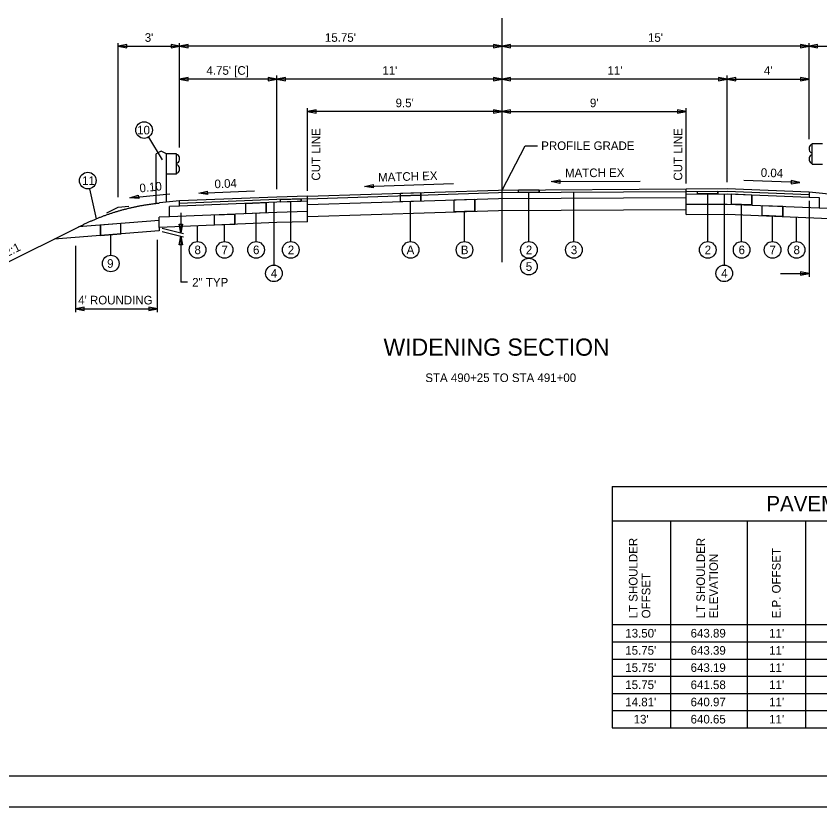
# Model space of a CAD drawing. Extents: x 0 to 102, y 0 to 66.
# Drawn here: x 34 to 73.27, y 0 to 38.63 of the extents above; entities that cross this region are included whole.
import ezdxf

# ---------------------------------------------------------------- set-up
doc = ezdxf.new("R2010")
doc.units = 0
for name, color, linetype in [('SH_Border', 7, 'Continuous'), ('SH_Cut_Line', 7, 'Continuous'), ('SH_Data', 7, 'Continuous'), ('SH_Text', 7, 'Continuous'), ('TX_P_1', 7, 'Continuous'), ('TX_X_1', 7, 'Continuous'), ('XS_P_Finished_Grade', 7, 'Continuous'), ('XS_P_Pavt_Surface', 7, 'Continuous'), ('XS_X_Pavt', 7, 'Continuous')]:
    doc.layers.add(name, color=color, linetype=linetype)

msp = doc.modelspace()

# ---------------------------------------------------------------- linework, layer by layer
at = {"layer": 'SH_Border'}
msp.add_lwpolyline([(4.5, 64.5), (100.5, 64.5), (100.5, 1.5), (4.5, 1.5)], close=True, dxfattribs=at)
at = {"layer": 'SH_Cut_Line'}
msp.add_lwpolyline([(0, 0), (102, 0), (102, 66), (0, 66)], close=True, dxfattribs=at)
at = {"layer": 'TX_P_1'}
for p, q in [((38.992, 29.793), (38.992, 37.304)), ((38.992, 37.166), (41.992, 37.166)), ((39.412, 37.082), (39.412, 37.25)), ((41.572, 37.25), (41.572, 37.082)), ((41.572, 37.25), (41.572, 37.082)), ((41.992, 32.207), (41.992, 37.304)), ((57.742, 37.166), (41.992, 37.166)), ((42.412, 37.082), (42.412, 37.25)), ((57.322, 37.25), (57.322, 37.082)), ((72.742, 37.166), (57.742, 37.166)), ((58.162, 37.082), (58.162, 37.25)), ((72.322, 37.25), (72.322, 37.082)), ((72.742, 32.62), (72.742, 37.304)), ((72.742, 37.166), (75.742, 37.166)), ((73.162, 37.082), (73.162, 37.25)), ((46.742, 35.557), (41.992, 35.557)), ((42.412, 35.473), (42.412, 35.641)), ((46.322, 35.641), (46.322, 35.473)), ((46.742, 30.182), (46.742, 35.728)), ((57.742, 35.557), (46.742, 35.557)), ((47.162, 35.473), (47.162, 35.641)), ((57.322, 35.641), (57.322, 35.473)), ((68.742, 35.557), (57.742, 35.557)), ((58.162, 35.473), (58.162, 35.641)), ((68.322, 35.641), (68.322, 35.473)), ((68.742, 30.527), (68.742, 35.728)), ((68.742, 35.557), (72.742, 35.557)), ((69.162, 35.473), (69.162, 35.641)), ((72.322, 35.641), (72.322, 35.473)), ((48.242, 30.101), (48.242, 34.133)), ((57.742, 33.972), (48.242, 33.972)), ((48.662, 33.888), (48.662, 34.056)), ((57.322, 34.056), (57.322, 33.888)), ((57.742, 33.972), (66.742, 33.972)), ((58.162, 33.888), (58.162, 34.056)), ((66.322, 34.056), (66.322, 33.888)), ((66.742, 30.461), (66.742, 34.133)), ((57.742, 30.137), (58.87, 32.301)), ((58.87, 32.301), (59.476, 32.301)), ((51.023, 30.312), (55.366, 30.45)), ((51.44, 30.409), (51.446, 30.241)), ((60.144, 30.545), (64.489, 30.571)), ((60.564, 30.631), (60.565, 30.463)), ((72.288, 30.499), (69.56, 30.608)), ((71.872, 30.6), (71.865, 30.432)), ((39.564, 29.757), (41.517, 29.952)), ((39.973, 29.882), (39.99, 29.715)), ((42.927, 29.98), (45.655, 30.089)), ((43.343, 30.081), (43.35, 29.913)), ((52.777, 29.567), (52.777, 29.984)), ((53.777, 29.599), (53.777, 30.015)), ((58.553, 30.017), (58.553, 30.142)), ((59.553, 30.023), (59.553, 30.148)), ((55.409, 29.067), (55.409, 29.651)), ((56.409, 29.099), (56.409, 29.682)), ((72.742, 29.608), (72.742, 25.893)), ((42.053, 29.022), (42.053, 28.049)), ((40.992, 28.647), (37.051, 28.331)), ((40.992, 28.312), (40.992, 28.145)), ((41.132, 28.277), (42.172, 28.019)), ((41.969, 28.469), (42.137, 28.469)), ((40.992, 28.145), (35.857, 27.734)), ((41.132, 28.11), (42.178, 27.851)), ((40.914, 24.172), (40.914, 27.706)), ((42.053, 27.882), (42.053, 25.63)), ((36.914, 24.172), (36.914, 27.403)), ((42.137, 27.462), (41.969, 27.462)), ((71.35, 26.062), (72.742, 26.062)), ((72.322, 26.146), (72.322, 25.978)), ((42.373, 25.63), (42.053, 25.63)), ((37.334, 24.254), (37.334, 24.422)), ((40.494, 24.422), (40.494, 24.254)), ((36.914, 24.338), (40.914, 24.338)), ((63.115, 15.657), (63.115, 3.866)), ((63.115, 15.657), (93.265, 15.657)), ((63.115, 13.977), (93.265, 13.977)), ((65.965, 13.977), (65.965, 3.866)), ((69.715, 13.977), (69.715, 3.866)), ((72.565, 13.977), (72.565, 3.866)), ((63.115, 8.906), (93.265, 8.906)), ((63.115, 8.066), (93.265, 8.066)), ((63.115, 7.226), (93.265, 7.226)), ((63.115, 6.386), (93.265, 6.386)), ((63.115, 5.546), (93.265, 5.546)), ((63.115, 4.706), (93.265, 4.706)), ((63.115, 3.866), (93.265, 3.866))]:
    msp.add_line(p, q, dxfattribs=at)
for points in [[(39.412, 37.25), (38.992, 37.166), (39.412, 37.082)], [(41.572, 37.082), (41.992, 37.166), (41.572, 37.25)], [(41.572, 37.082), (41.992, 37.166), (41.572, 37.25)], [(42.412, 37.25), (41.992, 37.166), (42.412, 37.082)], [(57.322, 37.082), (57.742, 37.166), (57.322, 37.25)], [(58.162, 37.25), (57.742, 37.166), (58.162, 37.082)], [(72.322, 37.082), (72.742, 37.166), (72.322, 37.25)], [(73.162, 37.25), (72.742, 37.166), (73.162, 37.082)], [(42.412, 35.641), (41.992, 35.557), (42.412, 35.473)], [(46.322, 35.473), (46.742, 35.557), (46.322, 35.641)], [(47.162, 35.641), (46.742, 35.557), (47.162, 35.473)], [(57.322, 35.473), (57.742, 35.557), (57.322, 35.641)], [(58.162, 35.641), (57.742, 35.557), (58.162, 35.473)], [(68.322, 35.473), (68.742, 35.557), (68.322, 35.641)], [(69.162, 35.641), (68.742, 35.557), (69.162, 35.473)], [(72.322, 35.473), (72.742, 35.557), (72.322, 35.641)], [(48.662, 34.056), (48.242, 33.972), (48.662, 33.888)], [(57.322, 33.888), (57.742, 33.972), (57.322, 34.056)], [(58.162, 34.056), (57.742, 33.972), (58.162, 33.888)], [(66.322, 33.888), (66.742, 33.972), (66.322, 34.056)], [(51.446, 30.241), (51.023, 30.312), (51.44, 30.409)], [(60.565, 30.463), (60.144, 30.545), (60.564, 30.631)], [(71.865, 30.432), (72.288, 30.499), (71.872, 30.6)], [(39.99, 29.715), (39.564, 29.757), (39.973, 29.882)], [(43.35, 29.913), (42.927, 29.98), (43.343, 30.081)], [(38.428, 29.02), (38.992, 29.302), (39.51, 29.354)], [(42.137, 28.469), (42.053, 28.049), (41.969, 28.469)], [(41.969, 27.462), (42.053, 27.882), (42.137, 27.462)], [(72.322, 25.978), (72.742, 26.062), (72.322, 26.146)], [(37.334, 24.422), (36.914, 24.338), (37.334, 24.254)], [(40.494, 24.254), (40.914, 24.338), (40.494, 24.422)]]:
    msp.add_lwpolyline(points, dxfattribs=at)
for points in [[(52.777, 29.984), (53.777, 30.015), (53.777, 29.89), (52.777, 29.859)], [(53.777, 29.599), (52.777, 29.567), (52.777, 29.859), (53.777, 29.89)], [(59.553, 30.023), (58.553, 30.017), (58.553, 30.142), (59.553, 30.148)], [(56.409, 29.682), (56.409, 29.099), (55.409, 29.067), (55.409, 29.651)]]:
    msp.add_lwpolyline(points, close=True, dxfattribs=at)
for centre in [(40.253, 33.064), (37.504, 30.597), (42.867, 27.212), (44.188, 27.212), (45.726, 27.212), (47.422, 27.212), (53.277, 27.212), (55.909, 27.212), (59.053, 27.212), (61.252, 27.212), (67.791, 27.212), (69.449, 27.212), (70.959, 27.212), (72.135, 27.212), (38.623, 26.547), (59.053, 26.399), (46.596, 26.066), (68.598, 26.066)]:
    msp.add_circle(centre, 0.406, dxfattribs=at)
at = {"layer": 'TX_X_1'}
for p, q in [((57.742, 26.608), (57.742, 38.528)), ((40.465, 32.717), (41.143, 31.614)), ((37.593, 30.2), (37.921, 28.733)), ((59.053, 27.618), (59.053, 30.02)), ((61.252, 27.618), (61.252, 30.033)), ((67.291, 29.945), (67.291, 30.07)), ((67.791, 27.618), (67.791, 29.948)), ((68.291, 29.951), (68.291, 30.076)), ((68.598, 29.953), (68.598, 26.472)), ((68.949, 29.445), (68.949, 29.945)), ((69.949, 29.405), (69.949, 29.905)), ((45.226, 28.981), (45.226, 29.481)), ((46.226, 29.021), (46.226, 29.521)), ((46.596, 29.536), (46.596, 26.472)), ((46.922, 29.548), (46.922, 29.673)), ((47.422, 27.618), (47.422, 29.563)), ((47.922, 29.579), (47.922, 29.704)), ((53.277, 27.618), (53.277, 29.583)), ((55.909, 27.618), (55.909, 29.083)), ((69.449, 27.618), (69.449, 29.425)), ((70.459, 28.885), (70.459, 29.385)), ((71.459, 28.845), (71.459, 29.345)), ((43.688, 28.42), (43.688, 28.92)), ((44.688, 28.46), (44.688, 28.96)), ((45.726, 27.618), (45.726, 29.001)), ((70.959, 27.618), (70.959, 28.865)), ((72.135, 27.618), (72.135, 28.818)), ((38.123, 27.916), (38.123, 28.417)), ((39.123, 27.996), (39.123, 28.497)), ((42.867, 27.618), (42.867, 28.387)), ((44.188, 27.618), (44.188, 28.44)), ((38.623, 26.953), (38.623, 27.956))]:
    msp.add_line(p, q, dxfattribs=at)
for points in [[(48.242, 29.839), (57.57, 30.136), (66.742, 30.192)], [(48.242, 29.423), (57.57, 29.719), (66.742, 29.775)], [(48.242, 28.839), (57.57, 29.136), (66.742, 29.192)]]:
    msp.add_lwpolyline(points, dxfattribs=at)
for points in [[(68.291, 29.951), (67.291, 29.945), (67.291, 30.07), (68.291, 30.076)], [(69.949, 29.405), (68.949, 29.445), (68.949, 29.945), (69.949, 29.905)], [(45.226, 28.981), (45.226, 29.481), (46.226, 29.521), (46.226, 29.021)], [(46.922, 29.548), (46.922, 29.673), (47.922, 29.704), (47.922, 29.579)], [(71.459, 29.345), (71.459, 28.845), (70.459, 28.885), (70.459, 29.385)], [(44.688, 28.96), (44.688, 28.46), (43.688, 28.42), (43.688, 28.92)], [(38.123, 28.417), (38.123, 27.916), (39.123, 27.996), (39.123, 28.497)]]:
    msp.add_lwpolyline(points, close=True, dxfattribs=at)
at = {"layer": 'XS_P_Finished_Grade'}
for p, q in [((72.742, 30.043), (75.742, 29.743)), ((41.992, 29.602), (41.015, 29.504)), ((37.173, 28.392), (30.605, 25.108))]:
    msp.add_line(p, q, dxfattribs=at)
msp.add_spline([(37.173, 28.392), (37.243, 28.427), (37.313, 28.461), (37.383, 28.495), (37.454, 28.528), (37.524, 28.561), (37.595, 28.593), (37.666, 28.624), (37.737, 28.655), (37.808, 28.686), (37.88, 28.716), (37.951, 28.745), (38.023, 28.774), (38.095, 28.803), (38.167, 28.831), (38.239, 28.858), (38.311, 28.885), (38.384, 28.911), (38.456, 28.937), (38.529, 28.963), (38.602, 28.987), (38.675, 29.012), (38.748, 29.035), (38.822, 29.059), (38.895, 29.081), (38.969, 29.103), (39.043, 29.125), (39.117, 29.146), (39.191, 29.167), (39.265, 29.187), (39.339, 29.206), (39.414, 29.225), (39.489, 29.244), (39.564, 29.262), (39.639, 29.279), (39.714, 29.296), (39.789, 29.313), (39.865, 29.329), (39.94, 29.344), (40.016, 29.359), (40.092, 29.373), (40.168, 29.387), (40.244, 29.4), (40.321, 29.413), (40.397, 29.425), (40.474, 29.437), (40.551, 29.448), (40.628, 29.459), (40.705, 29.469), (40.782, 29.478), (40.86, 29.488), (40.937, 29.496), (41.015, 29.504)], degree=3, dxfattribs=at)
at = {"layer": 'XS_P_Pavt_Surface'}
for p, q in [((66.742, 30.192), (68.742, 30.203)), ((66.742, 28.942), (66.742, 30.192)), ((66.742, 30.067), (68.742, 30.078)), ((66.742, 30.067), (68.742, 30.078)), ((66.742, 29.942), (68.742, 29.953)), ((68.742, 30.203), (72.742, 30.043)), ((68.742, 30.078), (72.742, 29.918)), ((68.742, 30.078), (72.742, 29.918)), ((68.742, 29.953), (72.742, 29.793)), ((72.742, 30.043), (72.742, 29.793)), ((46.742, 29.792), (41.992, 29.602)), ((46.742, 29.667), (41.992, 29.477)), ((46.742, 29.667), (41.992, 29.477)), ((41.992, 29.352), (41.992, 29.602)), ((46.742, 29.542), (41.992, 29.352)), ((48.242, 29.839), (46.742, 29.792)), ((48.242, 29.714), (46.742, 29.667)), ((48.242, 29.714), (46.742, 29.667)), ((48.242, 29.589), (46.742, 29.542)), ((48.242, 28.589), (48.242, 29.839)), ((72.742, 29.793), (73.242, 29.773)), ((73.242, 29.773), (73.242, 29.273)), ((41.992, 29.352), (41.492, 29.332)), ((41.492, 28.832), (41.492, 29.332)), ((48.242, 29.089), (46.742, 29.042)), ((66.742, 29.442), (68.742, 29.453)), ((68.742, 29.453), (73.242, 29.273)), ((73.242, 29.273), (73.742, 29.253)), ((41.492, 28.832), (40.992, 28.812)), ((40.992, 28.312), (40.992, 28.812)), ((46.742, 29.042), (41.492, 28.832)), ((66.742, 28.942), (68.742, 28.953)), ((68.742, 28.953), (73.742, 28.753)), ((46.742, 28.542), (40.992, 28.312)), ((48.242, 28.589), (46.742, 28.542))]:
    msp.add_line(p, q, dxfattribs=at)
for points in [[(48.242, 29.839), (57.57, 30.136), (66.742, 30.192)], [(48.242, 29.714), (57.57, 30.011), (66.742, 30.067)]]:
    msp.add_lwpolyline(points, dxfattribs=at)
at = {"layer": 'XS_X_Pavt'}
for p, q in [((72.842, 32.354), (72.892, 32.354)), ((72.892, 31.404), (72.892, 32.404)), ((72.892, 32.404), (73.392, 32.404)), ((41.092, 32.037), (40.842, 31.912)), ((40.842, 29.486), (40.842, 31.912)), ((41.342, 31.912), (41.092, 32.037)), ((41.842, 31.912), (41.342, 31.912)), ((41.342, 29.551), (41.342, 31.912)), ((41.842, 30.912), (41.842, 31.912)), ((41.892, 31.862), (41.842, 31.862)), ((72.842, 31.454), (72.892, 31.454)), ((72.892, 31.404), (73.392, 31.404)), ((41.842, 30.912), (41.342, 30.912)), ((41.892, 30.962), (41.842, 30.962))]:
    msp.add_line(p, q, dxfattribs=at)
for centre, radius, start, end in [((72.992, 32.154), 0.25, 126.8699, 233.1301), ((41.742, 31.662), 0.25, 306.8699, 53.1301), ((72.992, 31.654), 0.25, 126.8699, 233.1301), ((72.842, 31.904), 0.05, 270, 90), ((41.892, 31.412), 0.05, 90, 270), ((41.742, 31.162), 0.25, 306.8699, 53.1301)]:
    msp.add_arc(centre, radius, start, end, dxfattribs=at)

# ---------------------------------------------------------------- texts
at = {"layer": 'SH_Data'}
msp.add_text('PAVEMENT ELEVATION TABLE', height=0.75, dxfattribs=at).set_placement((70.656, 14.442))
at = {"layer": 'SH_Text'}
msp.add_text('WIDENING SECTION', height=0.84, dxfattribs=at).set_placement((51.952, 22.042))
at = {"layer": 'TX_P_1'}
for s, p in [("3'", (40.286, 37.376)), ("15.75'", (49.09, 37.376)), ("15'", (64.873, 37.376)), ("4.75' [C]", (43.302, 35.767)), ("11'", (51.895, 35.767)), ("11'", (62.895, 35.767)), ("4'", (70.536, 35.767)), ("9.5'", (52.542, 34.182)), ("9'", (62.036, 34.182)), ('10', (39.916, 32.854)), ('PROFILE GRADE', (59.657, 32.091)), ('11', (37.229, 30.387)), ('8', (42.717, 27.002)), ('7', (44.038, 27.002)), ('6', (45.576, 27.002)), ('2', (47.275, 27.002)), ('A', (53.081, 27.002)), ('B', (55.729, 27.002)), ('2', (58.905, 27.002)), ('3', (61.103, 27.002)), ('2', (67.643, 27.002)), ('6', (69.299, 27.002)), ('7', (70.809, 27.002)), ('8', (71.984, 27.002)), ('9', (38.449, 26.337)), ('5', (58.901, 26.189)), ('4', (46.447, 25.856)), ('4', (68.449, 25.856)), ('2" TYP', (42.605, 25.42)), ("4' ROUNDING", (37.034, 24.548)), ("13.50'", (63.764, 8.276)), ('643.89', (66.956, 8.276)), ("11'", (70.794, 8.276)), ("15.75'", (63.764, 7.436)), ('643.39', (66.956, 7.436)), ("11'", (70.794, 7.436)), ("15.75'", (63.764, 6.596)), ('643.19', (66.956, 6.596)), ("11'", (70.794, 6.596)), ("15.75'", (63.764, 5.756)), ('641.58', (66.956, 5.756)), ("11'", (70.794, 5.756)), ("14.81'", (63.764, 4.916)), ('640.97', (66.956, 4.916)), ("11'", (70.794, 4.916)), ("13'", (64.172, 4.076)), ('640.65', (66.955, 4.076)), ("11'", (70.794, 4.076))]:
    msp.add_text(s, height=0.42, dxfattribs=at).set_placement(p)
for s, rotation, p in [('CUT LINE', 90, (48.859, 30.597)), ('CUT LINE', 90, (66.546, 30.597)), ('MATCH EX', 1.82, (51.694, 30.543)), ('MATCH EX', 0.3504, (60.82, 30.759)), ('0.04', 357.7094, (70.376, 30.785)), ('0.04', 2.2906, (43.702, 30.221)), ('2:1', 26.5651, (33.563, 26.856)), ('LT SHOULDER', 90, (64.36, 9.212)), ('LT SHOULDER', 90, (67.66, 9.212)), ('E.P. OFFSET', 90, (71.35, 9.212)), ('ELEVATION', 90, (68.29, 9.212)), ('OFFSET', 90, (64.99, 9.212))]:
    msp.add_text(s, height=0.42, rotation=rotation, dxfattribs=at).set_placement(p)
at = {"layer": 'TX_X_1'}
msp.add_text('STA 490+25 TO STA 491+00', height=0.42, dxfattribs=at).set_placement((53.994, 20.756))
at = {"layer": 'XS_P_Finished_Grade'}
msp.add_text('0.10', height=0.42, rotation=5.7106, dxfattribs=at).set_placement((40.051, 30.016))

doc.saveas('drawing.dxf')
